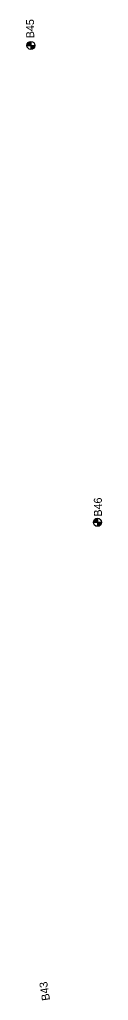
# Model space of a CAD drawing. Extents: x 345549 to 379569, y 127949 to 230467.
# Drawn here: x 360189 to 360283, y 153339 to 154565 of the extents above; entities that cross this region are included whole.
import ezdxf

# ---------------------------------------------------------------- set-up
doc = ezdxf.new("R2010")
doc.units = 0
for name, color, linetype in [('E_SOIL_BORE1 [KAPUR_CADDS_LEVELS]', 7, 'Continuous'), ('E_SOIL_BORE2 [KAPUR_CADDS_LEVELS]', 7, 'Continuous'), ('P_MARK', 7, 'Continuous')]:
    doc.layers.add(name, color=color, linetype=linetype)

msp = doc.modelspace()

# ---------------------------------------------------------------- linework, layer by layer
at = {"layer": 'P_MARK'}
for p, q in [((360194.7, 154537.2), (360194.7, 154527.2)), ((360189.7, 154532.2), (360199.7, 154532.2)), ((360272.6, 153936.2), (360282.6, 153936.2)), ((360277.6, 153941.2), (360277.6, 153931.2))]:
    msp.add_line(p, q, dxfattribs=at)
for centre in [(360194.7, 154532.2), (360277.6, 153936.2)]:
    msp.add_circle(centre, 5, dxfattribs=at)
for centre, radius, start, end in [((360194.7, 154532.2), 4.5, 89.9869, 179.9869), ((360194.7, 154532.2), 4, 89.9869, 179.9869), ((360194.7, 154532.2), 3.5, 89.9869, 179.9869), ((360194.7, 154532.2), 3, 89.9869, 179.9869), ((360194.7, 154532.2), 2.5, 89.9869, 179.9869), ((360194.7, 154532.2), 2, 89.9869, 179.9869), ((360194.7, 154532.2), 1.5, 89.9869, 179.9869), ((360194.7, 154532.2), 1, 89.9869, 179.9869), ((360194.7, 154532.2), 0.5, 89.9869, 179.9869), ((360194.7, 154532.2), 4.5, 269.9869, 359.9869), ((360194.7, 154532.2), 4, 269.9869, 359.9869), ((360194.7, 154532.2), 3.5, 269.9869, 359.9869), ((360194.7, 154532.2), 3, 269.9869, 359.9869), ((360194.7, 154532.2), 2.5, 269.9869, 359.9869), ((360194.7, 154532.2), 2, 269.9869, 359.9869), ((360194.7, 154532.2), 1.5, 269.9869, 359.9869), ((360194.7, 154532.2), 1, 269.9869, 359.9869), ((360194.7, 154532.2), 0.5, 269.9869, 359.9869), ((360277.6, 153936.2), 4.5, 89.9869, 179.9869), ((360277.6, 153936.2), 4, 89.9869, 179.9869), ((360277.6, 153936.2), 3.5, 89.9869, 179.9869), ((360277.6, 153936.2), 3, 89.9869, 179.9869), ((360277.6, 153936.2), 2.5, 89.9869, 179.9869), ((360277.6, 153936.2), 2, 89.9869, 179.9869), ((360277.6, 153936.2), 1.5, 89.9869, 179.9869), ((360277.6, 153936.2), 1, 89.9869, 179.9869), ((360277.6, 153936.2), 0.5, 89.9869, 179.9869), ((360277.6, 153936.2), 4.5, 269.9869, 359.9869), ((360277.6, 153936.2), 4, 269.9869, 359.9869), ((360277.6, 153936.2), 3.5, 269.9869, 359.9869), ((360277.6, 153936.2), 3, 269.9869, 359.9869), ((360277.6, 153936.2), 2.5, 269.9869, 359.9869), ((360277.6, 153936.2), 2, 269.9869, 359.9869), ((360277.6, 153936.2), 1.5, 269.9869, 359.9869), ((360277.6, 153936.2), 1, 269.9869, 359.9869), ((360277.6, 153936.2), 0.5, 269.9869, 359.9869)]:
    msp.add_arc(centre, radius, start, end, dxfattribs=at)

# ---------------------------------------------------------------- texts
at = {"layer": 'E_SOIL_BORE1 [KAPUR_CADDS_LEVELS]'}
msp.add_text('B43', height=10, rotation=98.8576, dxfattribs=at).set_placement((360218.6, 153339.1))
at = {"layer": 'E_SOIL_BORE2 [KAPUR_CADDS_LEVELS]'}
for s, p in [('B45', (360198.9, 154541.3)), ('B46', (360283.3, 153943.4))]:
    msp.add_text(s, height=10, rotation=90.6368, dxfattribs=at).set_placement(p)

doc.saveas('drawing.dxf')
